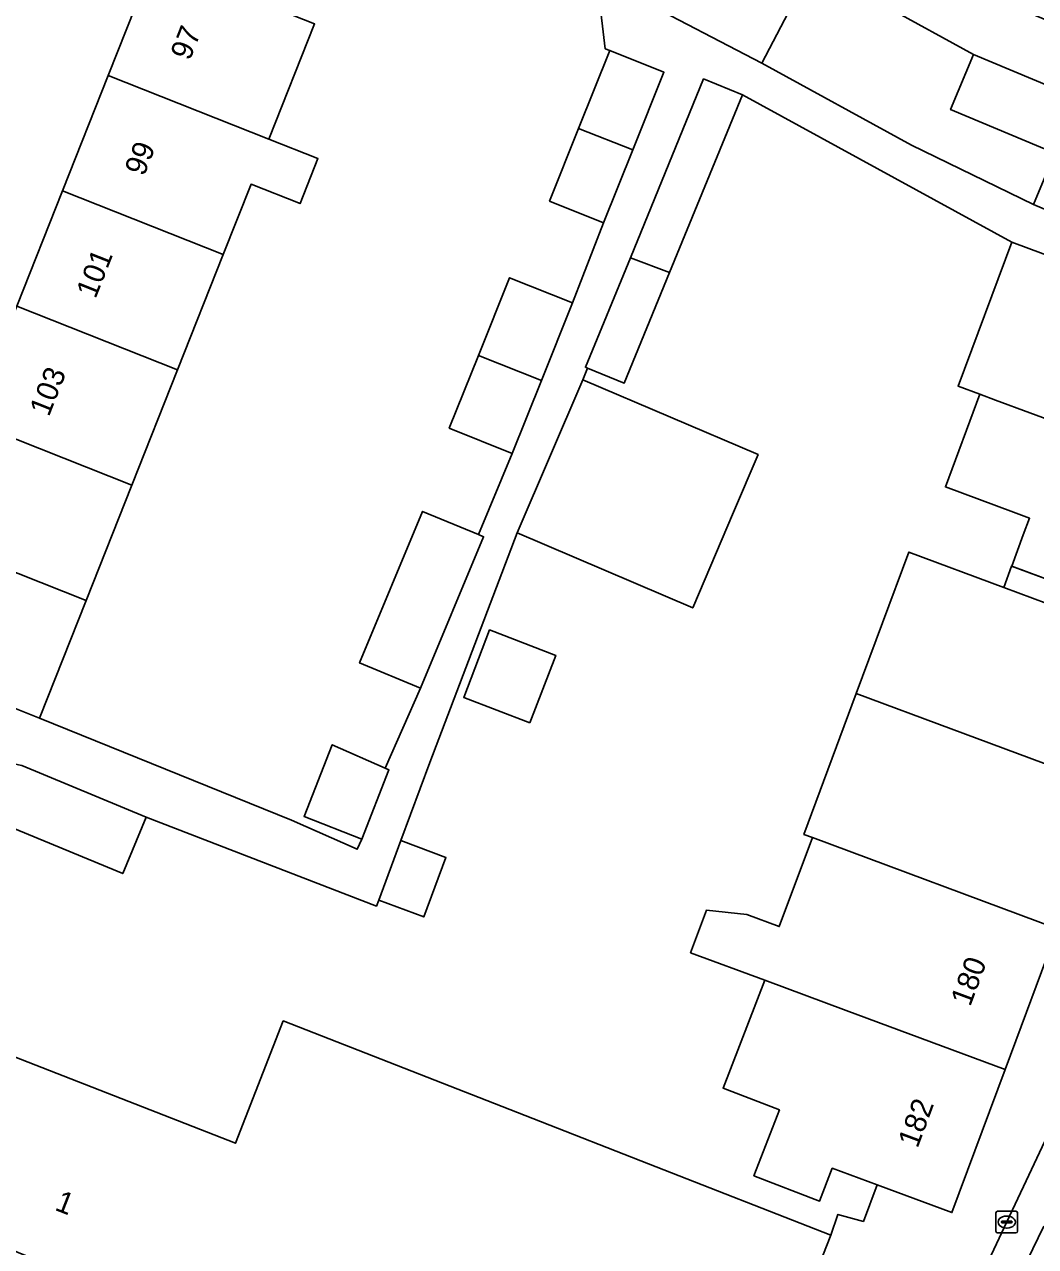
# Model space of a CAD drawing. Extents: x 160349 to 161355, y 381727 to 382854.
# Drawn here: x 160655.2 to 160702.1, y 382020.3 to 382077 of the extents above; entities that cross this region are included whole.
import ezdxf

# ---------------------------------------------------------------- set-up
doc = ezdxf.new("R2010")
doc.units = 0
for name, color, linetype in [('IMGEO_Erf', 7, 'Continuous'), ('IMGEO_Kolk', 7, 'Continuous'), ('IMGEO_Pand', 7, 'Continuous'), ('IMGEO_Pand_nummerreeks', 7, 'Continuous'), ('IMGEO_Pand_overbouw', 7, 'Continuous'), ('IMGEO_Rijbaan_lokaal_gesloten', 7, 'Continuous'), ('IMGEO_Voetpad_open', 7, 'Continuous')]:
    doc.layers.add(name, color=color, linetype=linetype)

msp = doc.modelspace()

# ---------------------------------------------------------------- linework, layer by layer
at = {"layer": 'IMGEO_Erf'}
for points in [[(160669.66, 382101.331), (160671.777, 382106.678), (160673.894, 382112.022), (160676.01, 382117.368), (160678.127, 382122.713), (160680.243, 382128.058), (160682.36, 382133.403), (160684.476, 382138.748), (160686.593, 382144.093), (160688.754, 382149.551), (160683.199, 382151.736), (160672.819, 382125.35), (160661.371, 382096.521), (160642.897, 382049.998), (160648.453, 382047.774), (160650.611, 382053.225), (160652.728, 382058.571), (160654.845, 382063.916), (160656.961, 382069.26), (160659.078, 382074.606), (160661.194, 382079.95), (160663.311, 382085.296), (160665.428, 382090.642), (160667.544, 382095.987)], [(160678.63, 382044.608), (160675.566, 382045.786), (160676.767, 382048.912), (160679.831, 382047.734)]]:
    msp.add_lwpolyline(points, close=True, dxfattribs=at)
for points in [[(160691.661, 382079.533), (160689.391, 382075.184), (160696.328, 382071.375), (160701.97, 382068.631), (160702.96, 382071.014), (160698.134, 382073.028), (160699.198, 382075.578), (160695.196, 382077.779)], [(160668.648, 382077.001), (160666.532, 382071.656), (160668.808, 382070.755), (160667.983, 382068.67), (160665.706, 382069.571), (160664.415, 382066.311), (160662.298, 382060.966), (160660.182, 382055.622), (160658.065, 382050.276), (160655.906, 382044.823), (160667.588, 382040.103), (160670.629, 382038.753), (160670.837, 382039.222), (160668.166, 382040.275), (160669.473, 382043.591), (160671.922, 382042.504), (160673.567, 382046.208), (160670.741, 382047.382), (160673.66, 382054.409), (160676.255, 382053.331), (160677.818, 382057.093), (160674.894, 382058.265), (160676.243, 382061.631), (160677.687, 382065.237), (160680.611, 382064.066), (160682.051, 382067.783), (160679.543, 382068.788), (160680.892, 382072.157), (160682.335, 382075.761), (160682.125, 382075.845), (160681.832, 382078.34)], [(160703.633, 382050.879), (160700.966, 382051.87), (160701.506, 382053.323), (160701.792, 382054.092), (160701.045, 382054.37), (160697.898, 382055.541), (160699.496, 382059.835), (160698.485, 382060.211), (160700.966, 382066.882), (160688.488, 382073.712), (160685.111, 382065.476), (160683.01, 382060.351), (160681.304, 382061.051), (160681.083, 382060.512), (160689.212, 382057.039), (160688.071, 382054.367), (160686.179, 382049.938), (160678.049, 382053.412), (160673.989, 382042.767), (160672.647, 382039.15), (160674.74, 382038.374), (160673.716, 382035.613), (160671.623, 382036.389), (160671.521, 382036.114), (160660.842, 382040.237), (160659.757, 382037.624), (160654.494, 382039.809)], [(160652.031, 382030.186), (160664.979, 382025.121), (160667.199, 382030.796), (160678.768, 382026.27), (160684.128, 382024.173), (160692.577, 382020.868), (160692.91, 382021.824), (160694.093, 382021.5), (160694.723, 382023.198), (160692.649, 382023.969), (160692.06, 382022.444), (160689.019, 382023.617), (160690.197, 382026.672), (160687.591, 382027.678), (160689.52, 382032.679), (160686.083, 382033.957), (160686.815, 382035.925), (160688.694, 382035.727), (160690.193, 382035.169), (160691.727, 382039.294), (160691.334, 382039.44), (160693.761, 382045.963), (160696.2, 382052.521), (160700.595, 382050.888), (160703.267, 382049.895)]]:
    msp.add_lwpolyline(points, dxfattribs=at)
at = {"layer": 'IMGEO_Kolk'}
for p, q in [((160700.238, 382021.047), (160700.238, 382021.899)), ((160700.313, 382021.973), (160701.165, 382021.973)), ((160700.497, 382021.467), (160700.497, 382021.479)), ((160700.54, 382021.516), (160700.938, 382021.516)), ((160700.726, 382021.753), (160700.751, 382021.753)), ((160700.981, 382021.479), (160700.981, 382021.467)), ((160701.239, 382021.899), (160701.239, 382021.047)), ((160701.165, 382020.973), (160700.313, 382020.973)), ((160700.935, 382021.43), (160700.537, 382021.43)), ((160700.749, 382021.193), (160700.724, 382021.193))]:
    msp.add_line(p, q, dxfattribs=at)
for points in [[(160700.238, 382021.047), (160700.238, 382021.899)], [(160700.313, 382021.973), (160701.165, 382021.973)], [(160701.239, 382021.899), (160701.239, 382021.047)], [(160701.165, 382020.973), (160700.313, 382020.973)]]:
    msp.add_lwpolyline(points, dxfattribs=at)
for centre, radius, start, end in [((160700.315, 382021.897), 0.0765, 91.552, 178.448), ((160700.315, 382021.897), 0.0765, 91.552, 178.448), ((160700.537, 382021.476), 0.0403, 85.8775, 175.7526), ((160700.534, 382021.466), 0.0366, 178.938, 274.7102), ((160700.938, 382021.473), 0.043, 264.8664, 352.4533), ((160700.942, 382021.478), 0.0386, 1.7309, 96.639), ((160701.163, 382021.897), 0.0765, 1.552, 88.448), ((160701.163, 382021.897), 0.0765, 1.552, 88.448), ((160700.315, 382021.049), 0.0765, 181.552, 268.448), ((160700.315, 382021.049), 0.0765, 181.552, 268.448), ((160701.163, 382021.049), 0.0765, 271.552, 358.448), ((160701.163, 382021.049), 0.0765, 271.552, 358.448)]:
    msp.add_arc(centre, radius, start, end, dxfattribs=at)
for centre, major_axis, ratio, start_param, end_param in [((160700.725, 382021.473), (-0.387, 0.002), 0.722429, 4.712389, 7.853982), ((160700.75, 382021.473), (-0.39, 0.002), 0.717154, 1.570796, 4.712389)]:
    msp.add_ellipse(centre, major_axis=major_axis, ratio=ratio, start_param=start_param, end_param=end_param, dxfattribs=at)
at = {"layer": 'IMGEO_Pand'}
for points in [[(160685.905, 382082.561), (160683.626, 382078.193), (160689.391, 382075.184), (160691.661, 382079.533)], [(160661.194, 382079.95), (160659.078, 382074.606), (160666.532, 382071.656), (160668.648, 382077.001)], [(160700.271, 382078.147), (160696.423, 382080.009), (160695.196, 382077.779), (160699.198, 382075.578), (160711.651, 382070.378), (160713.624, 382075.104), (160705.911, 382078.324), (160705.011, 382076.169)], [(160684.844, 382074.756), (160682.335, 382075.761), (160680.892, 382072.157), (160683.405, 382071.163)], [(160699.198, 382075.578), (160698.134, 382073.028), (160702.96, 382071.014), (160701.97, 382068.631), (160704.977, 382067.37), (160709.591, 382065.444), (160711.651, 382070.378)], [(160666.532, 382071.656), (160659.078, 382074.606), (160656.961, 382069.26), (160664.415, 382066.311), (160665.706, 382069.571), (160667.983, 382068.67), (160668.808, 382070.755)], [(160685.111, 382065.476), (160688.488, 382073.712), (160686.686, 382074.451), (160683.289, 382066.165)], [(160683.405, 382071.163), (160680.892, 382072.157), (160679.543, 382068.788), (160682.051, 382067.783)], [(160664.415, 382066.311), (160656.961, 382069.26), (160654.845, 382063.916), (160662.298, 382060.966)], [(160713.224, 382062.323), (160712.982, 382062.413), (160708.538, 382064.066), (160705.874, 382065.057), (160700.966, 382066.882), (160698.485, 382060.211), (160699.496, 382059.835), (160700.215, 382059.568), (160703.393, 382058.386), (160710.773, 382055.733)], [(160685.111, 382065.476), (160683.289, 382066.165), (160681.208, 382061.09), (160681.304, 382061.051), (160683.01, 382060.351)], [(160676.243, 382061.631), (160679.172, 382060.472), (160680.611, 382064.066), (160677.687, 382065.237)], [(160660.182, 382055.622), (160662.298, 382060.966), (160654.845, 382063.916), (160652.728, 382058.571)], [(160676.243, 382061.631), (160674.894, 382058.265), (160677.818, 382057.093), (160679.172, 382060.472)], [(160689.212, 382057.039), (160681.083, 382060.512), (160678.049, 382053.412), (160686.179, 382049.938), (160688.071, 382054.367)], [(160710.773, 382055.733), (160703.393, 382058.386), (160700.215, 382059.568), (160699.496, 382059.835), (160697.898, 382055.541), (160701.045, 382054.37), (160701.792, 382054.092), (160701.506, 382053.323), (160700.966, 382051.87), (160703.633, 382050.879), (160708.319, 382049.136)], [(160660.182, 382055.622), (160652.728, 382058.571), (160650.611, 382053.225), (160658.065, 382050.276)], [(160676.486, 382053.235), (160676.255, 382053.331), (160673.66, 382054.409), (160670.741, 382047.382), (160673.567, 382046.208)], [(160658.065, 382050.276), (160650.611, 382053.225), (160648.453, 382047.774), (160653.102, 382045.933), (160655.906, 382044.823)], [(160705.513, 382041.591), (160707.953, 382048.152), (160703.267, 382049.895), (160700.595, 382050.888), (160696.2, 382052.521), (160693.761, 382045.963), (160698.155, 382044.328)], [(160678.63, 382044.608), (160679.831, 382047.734), (160676.767, 382048.912), (160675.566, 382045.786)], [(160705.513, 382041.591), (160698.155, 382044.328), (160693.761, 382045.963), (160691.334, 382039.44), (160691.727, 382039.294), (160703.087, 382035.068)], [(160672.099, 382042.425), (160671.922, 382042.504), (160669.473, 382043.591), (160668.166, 382040.275), (160670.837, 382039.222)], [(160672.647, 382039.15), (160671.623, 382036.389), (160673.716, 382035.613), (160674.74, 382038.374)], [(160703.087, 382035.068), (160691.727, 382039.294), (160690.193, 382035.169), (160688.694, 382035.727), (160686.815, 382035.925), (160686.083, 382033.957), (160689.52, 382032.679), (160693.3, 382031.273), (160700.657, 382028.536)], [(160700.657, 382028.536), (160693.3, 382031.273), (160689.52, 382032.679), (160687.591, 382027.678), (160690.197, 382026.672), (160689.019, 382023.617), (160692.06, 382022.444), (160692.649, 382023.969), (160694.723, 382023.198), (160698.192, 382021.908)]]:
    msp.add_lwpolyline(points, close=True, dxfattribs=at)
msp.add_lwpolyline([(160690.483, 382015.514), (160692.577, 382020.868), (160684.128, 382024.173), (160678.768, 382026.27), (160667.199, 382030.796), (160664.979, 382025.121), (160652.031, 382030.186), (160653.21, 382033.201), (160653.948, 382033.048), (160654.668, 382036.531), (160653.852, 382036.7), (160654.494, 382039.809), (160659.757, 382037.624), (160660.842, 382040.237), (160655.077, 382042.63), (160650.024, 382043.674), (160648.07, 382034.218), (160650.519, 382033.712), (160649.533, 382031.191), (160648.069, 382031.763), (160645.111, 382024.031), (160660.58, 382017.753)], dxfattribs=at)
at = {"layer": 'IMGEO_Pand_overbouw'}
msp.add_lwpolyline([(160700.595, 382050.888), (160703.267, 382049.895), (160707.953, 382048.152), (160708.319, 382049.136), (160703.633, 382050.879), (160700.961, 382051.872)], close=True, dxfattribs=at)
at = {"layer": 'IMGEO_Rijbaan_lokaal_gesloten'}
for points in [[(160703.636, 382027.62), (160699.26, 382018.335), (160698.861, 382017.487), (160693.954, 382007.485), (160695.412, 382006.702), (160700.139, 382016.515), (160702.456, 382021.28)], [(160702.456, 382021.28), (160700.139, 382016.515), (160695.412, 382006.702), (160693.954, 382007.485), (160693.164, 382005.874), (160692.978, 382005.495), (160692.495, 382004.543), (160690.234, 382000), (160685.331, 381988.306), (160685.061, 381987.613), (160684.901, 381987.296), (160664.1, 381935.204), (160663.187, 381932.992), (160662.012, 381930.058), (160661.794, 381929.458)]]:
    msp.add_lwpolyline(points, dxfattribs=at)
at = {"layer": 'IMGEO_Voetpad_open'}
for points in [[(160704.977, 382067.37), (160701.97, 382068.631), (160696.328, 382071.375), (160689.391, 382075.184), (160683.626, 382078.193), (160685.905, 382082.561), (160686.167, 382083.054), (160685.93, 382083.18), (160688.43, 382087.889), (160690.773, 382092.304), (160691.048, 382092.76), (160690.776, 382092.924), (160693.107, 382097.731), (160693.141, 382097.801), (160695.79, 382103.252), (160698.655, 382109.15), (160701.506, 382115.018), (160701.766, 382114.909), (160706.387, 382123.75)], [(160681.832, 382078.34), (160682.125, 382075.845), (160682.335, 382075.761), (160684.844, 382074.756), (160683.405, 382071.163), (160682.051, 382067.783), (160680.611, 382064.066), (160679.172, 382060.472), (160677.818, 382057.093), (160676.255, 382053.331), (160676.486, 382053.235), (160673.567, 382046.208), (160671.922, 382042.504), (160672.099, 382042.425), (160670.837, 382039.222), (160670.629, 382038.753), (160667.588, 382040.103), (160655.906, 382044.823), (160653.102, 382045.933)], [(160655.077, 382042.63), (160660.842, 382040.237), (160671.521, 382036.114), (160671.623, 382036.389), (160672.647, 382039.15), (160673.989, 382042.767), (160678.049, 382053.412), (160681.083, 382060.512), (160681.304, 382061.051), (160681.208, 382061.09), (160683.289, 382066.165), (160686.686, 382074.451), (160688.488, 382073.712), (160700.966, 382066.882), (160705.874, 382065.057)], [(160703.087, 382035.068), (160700.657, 382028.536), (160698.192, 382021.908), (160694.723, 382023.198), (160694.093, 382021.5), (160692.91, 382021.824), (160692.577, 382020.868), (160690.483, 382015.514), (160690.292, 382015.025), (160688.056, 382015.9), (160687.548, 382014.601), (160688.566, 382014.202), (160687.207, 382010.728), (160686.323, 382008.467), (160688.035, 382007.694)], [(160699.26, 382018.335), (160703.636, 382027.62), (160704.223, 382028.902)]]:
    msp.add_lwpolyline(points, dxfattribs=at)

# ---------------------------------------------------------------- texts
at = {"layer": 'IMGEO_Pand_nummerreeks'}
for s, rotation, p in [('97', 68.3977, (160662.864, 382075.26)), ('99', 68.3997, (160660.743, 382069.903)), ('101', 68.3977, (160658.495, 382064.224)), ('103', 68.3977, (160656.332, 382058.761)), ('180', 69.5972, (160699.043, 382031.424)), ('182', 69.5972, (160696.601, 382024.858)), ('1', 338.6348, (160656.563, 382022.047))]:
    msp.add_text(s, height=1, rotation=rotation, dxfattribs=at).set_placement(p)

doc.saveas('drawing.dxf')
